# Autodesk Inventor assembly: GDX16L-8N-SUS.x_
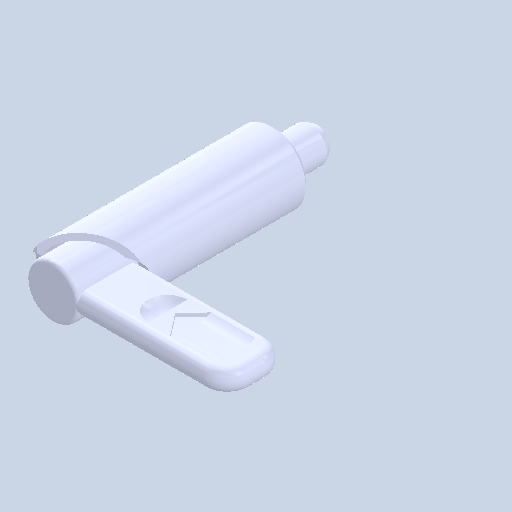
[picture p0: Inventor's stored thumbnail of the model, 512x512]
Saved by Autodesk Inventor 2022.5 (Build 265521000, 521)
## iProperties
Created: 2024-06
Part Number: GDX16L-8N-SUS.x_
Document SubType Name: Assembly
Designer: ImaoCorp
Author: ImaoCorp
Sending System: SOLIDWORKS 2022-2022290
MC: AMD64
MC_MODEL: Intel64 Family 6 Model 60 Stepping 3, GenuineIntel
OS: Windows_NT
FRU: Parasolid Version 33.1, build 260,  4-25-2022
FORMAT: text
GUISE: transmit
KEY: FILEGDX16L-8N-SUS.x_t
DATE: Wed Jun 12 09:32:24 2024
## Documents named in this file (3)
- Y:\5.更新分\2024年対応\xxxx_GDX\データ_imao品番\gdx16l-8n-sus\GDX16L-8N-SUS.x_.iam
- Y:\5.更新分\2024年対応\xxxx_GDX\データ_imao品番\gdx16l-8n-sus\GDX16L-8N-SUS_01.ipt
- Y:\5.更新分\2024年対応\xxxx_GDX\データ_imao品番\gdx16l-8n-sus\GDX16L-8N-SUS_02.ipt
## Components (2 placed, 2 different names)
1. GDX16L-8N-SUS_01
2. GDX16L-8N-SUS_02
